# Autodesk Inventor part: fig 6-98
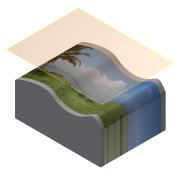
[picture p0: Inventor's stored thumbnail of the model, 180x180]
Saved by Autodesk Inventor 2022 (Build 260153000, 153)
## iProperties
Created: 2012-08
Part Number: fig 6-98
Material: Generic
Document SubType Name: Modeling
Designer: CADCIM
Density: 1 g/cm^3
Appearance: Default
Author: CADCIM
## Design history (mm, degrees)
sketch "Sketch1"
  geometry: L1 (0, 0)-(0, 12.146); L2 (32.23, 12.146)-(32.23, 0); L3 (32.23, 0)-(0, 0); 5 further points
  constraints: 6 end point, 1 parallel, 1 perpendicular, 1 vertical, 7 other
extrude "Extrusion1" new body sketch "Sketch1" distance "d0" = 24.5; taper "d1" = 0 deg
workplane "Work Plane1"
fillet "Fillet1" dims "d19" = 2
sketch "Sketch2"
  geometry: L1 (-33.343, 22.666)-(0.669, 22.666); L2 (0.669, 22.666)-(0.669, 1.409); L3 (0.669, 1.409)-(-33.343, 1.409); L4 (-33.343, 1.409)-(-33.343, 22.666); 1 other entity
  constraints: 2 other
feature "Decal1" sketch "Sketch2"
body "Solid1"
node "Image1"
other parameters: "d2" = 22
